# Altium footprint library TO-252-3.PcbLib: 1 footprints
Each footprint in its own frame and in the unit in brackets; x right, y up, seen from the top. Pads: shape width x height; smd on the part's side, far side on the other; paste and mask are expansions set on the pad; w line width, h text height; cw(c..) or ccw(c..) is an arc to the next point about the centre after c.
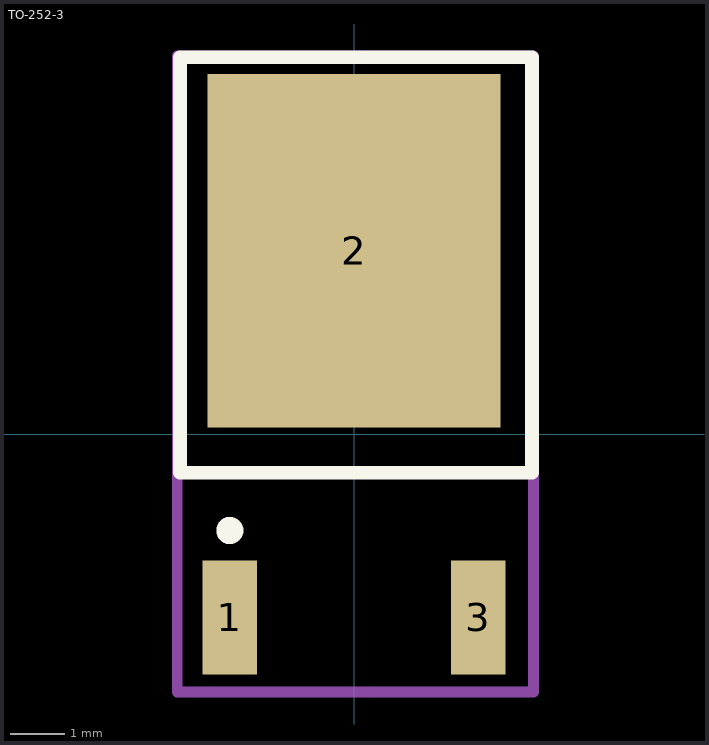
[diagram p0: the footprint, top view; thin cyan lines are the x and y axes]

## TO-252-3 [mm] "D-PAK/TO-252-AA; 3 Leads (1 Cropped); Body 10.1 (inc. leads) x 6.6 mm (LxW max)"
height 2.4
pads (3):
  rect 1x2.1 smd: 1(-2.285,-3.375) 3(2.285,-3.375)
  rect 5.4x6.5 smd: 2(0,3.375)
Top Overlay:
  circle w0.25: c-2.285,-1.775 r0.125
  lines w0.254: -3.2,-0.711 -3.2,6.934 3.277,6.934 3.277,5.802 3.277,-0.711 -3.2,-0.711
Mechanical 15:
  lines w0.2: -3.251,-4.75 3.302,-4.75 3.302,6.96 -3.251,6.96 -3.251,-4.75
3D body "DPAK_TO-252AA.STEP": height 2.37, standoff -0.03, extent -3.342,-3.826 3.392,6.274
